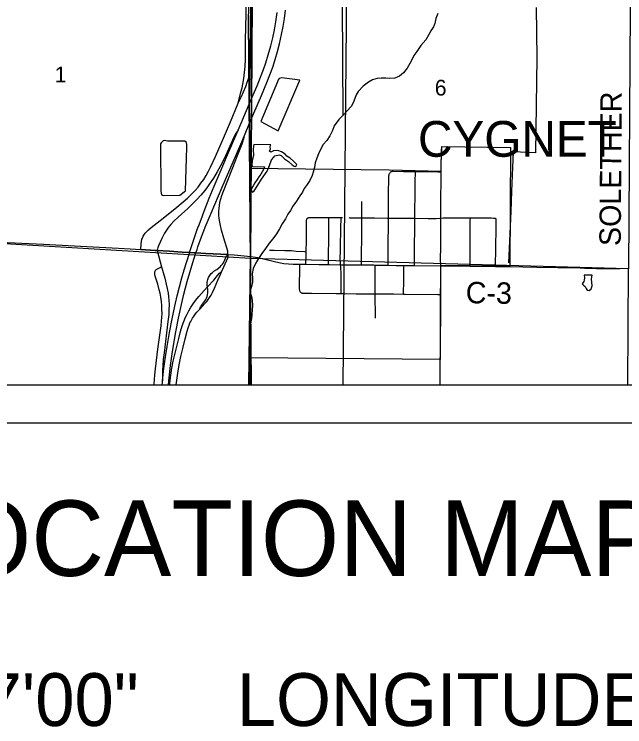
# Model space of a CAD drawing. Extents: x 0 to 39.4, y 0 to 22.
# Drawn here: x 4.739 to 6.358, y 13.194 to 15.083 of the extents above; entities that cross this region are included whole.
import ezdxf

# ---------------------------------------------------------------- set-up
doc = ezdxf.new("R2010")
doc.units = 0
for name, color, linetype in [('Default', 7, 'Continuous'), ('GM_X_City_Street', 7, 'Continuous'), ('GM_X_Corporation', 7, 'Continuous'), ('GM_X_Corporation_Text', 7, 'Continuous'), ('GM_X_County_Road', 7, 'Continuous'), ('GM_X_County_Road_Text', 7, 'Continuous'), ('GM_X_Interchange_Ramps', 7, 'Continuous'), ('GM_X_Interstate_Route', 7, 'Continuous'), ('GM_X_Minor_Lake', 7, 'Continuous'), ('GM_X_Minor_River', 7, 'Continuous'), ('GM_X_Rail_Line', 7, 'Continuous'), ('GM_X_Section', 7, 'Continuous'), ('GM_X_Section_Text', 7, 'Continuous'), ('GM_X_State_Route', 7, 'Continuous'), ('GM_X_Township_Road', 7, 'Continuous'), ('GM_X_Township_Road_Text', 7, 'Continuous'), ('SH_Data', 7, 'Continuous'), ('SH_Text', 7, 'Continuous')]:
    doc.layers.add(name, color=color, linetype=linetype)

msp = doc.modelspace()

# ---------------------------------------------------------------- linework, layer by layer
at = {"layer": 'Default'}
for points in [[(4.3575, 14.1), (5.3634, 14.1), (5.3657, 14.4352), (4.3571, 14.4954)], [(5.3634, 14.1), (6.3661, 14.1), (6.3684, 14.4076), (5.3657, 14.4352)]]:
    msp.add_lwpolyline(points, close=True, dxfattribs=at)
at = {"layer": 'GM_X_City_Street'}
for points in [[(5.7305, 14.4176), (5.7305, 14.4227), (5.7308, 14.4538), (5.7307, 14.4667), (5.731, 14.4898), (5.7313, 14.5091), (5.7313, 14.5284), (5.7313, 14.5424), (5.7313, 14.5469), (5.7315, 14.5599), (5.7316, 14.5731), (5.7318, 14.6079), (5.7319, 14.6212), (5.732, 14.6352), (5.732, 14.6481), (5.7324, 14.6544), (5.7329, 14.6574), (5.7333, 14.6589), (5.7339, 14.6603), (5.7347, 14.6617), (5.7355, 14.6629), (5.7366, 14.664), (5.7375, 14.6649), (5.7389, 14.6658), (5.7404, 14.6664)], [(5.7404, 14.6664), (5.7419, 14.6667), (5.7433, 14.6668), (5.7712, 14.666), (5.7957, 14.6657), (5.8028, 14.6658), (5.8171, 14.6658), (5.8351, 14.6659), (5.8477, 14.6656), (5.8624, 14.6654), (5.8711, 14.6652)], [(5.8003, 14.4168), (5.8003, 14.4203), (5.8003, 14.4287), (5.8002, 14.4336), (5.8002, 14.4376), (5.8004, 14.4507), (5.8004, 14.4588), (5.8005, 14.4667), (5.8006, 14.4744), (5.8009, 14.4879), (5.801, 14.4944), (5.801, 14.5018), (5.8012, 14.5109), (5.8012, 14.5162), (5.8012, 14.5217), (5.8013, 14.5316), (5.8013, 14.5419), (5.8013, 14.5434), (5.8013, 14.5531), (5.8015, 14.5623), (5.8017, 14.5686), (5.8017, 14.5772), (5.8019, 14.5881), (5.8021, 14.5959), (5.8022, 14.6022), (5.8022, 14.6051), (5.8021, 14.6092), (5.8022, 14.6256), (5.8025, 14.6473), (5.8027, 14.6566), (5.8027, 14.6597), (5.8028, 14.6658)], [(5.6598, 14.4184), (5.6598, 14.4235), (5.6598, 14.4266), (5.6601, 14.4579), (5.6603, 14.4798), (5.6604, 14.5143), (5.6605, 14.5393), (5.6605, 14.5433), (5.6607, 14.568), (5.6606, 14.5861)], [(5.5119, 14.4199), (5.5121, 14.425), (5.5127, 14.4404), (5.513, 14.4533), (5.5136, 14.4828), (5.514, 14.5289), (5.5141, 14.5345), (5.5142, 14.5366), (5.5144, 14.5384), (5.5147, 14.5401), (5.5153, 14.5416)], [(5.5153, 14.5416), (5.5162, 14.5424), (5.5174, 14.5431), (5.5188, 14.5436), (5.5204, 14.5439), (5.522, 14.5441), (5.5234, 14.5442), (5.5251, 14.5443), (5.5347, 14.5444), (5.5408, 14.5443), (5.5441, 14.5442), (5.5473, 14.5442), (5.5502, 14.5442), (5.5533, 14.5443), (5.569, 14.5442), (5.5734, 14.5441), (5.5972, 14.5438), (5.606, 14.5438), (5.6098, 14.5438)], [(5.5721, 14.4192), (5.5721, 14.4249), (5.5721, 14.4311), (5.5724, 14.4498), (5.5729, 14.4802), (5.573, 14.5019), (5.5733, 14.5358), (5.5734, 14.5441)], [(5.6045, 14.4188), (5.6041, 14.4227), (5.6037, 14.4265), (5.6036, 14.4294), (5.6041, 14.462), (5.6051, 14.518), (5.6059, 14.5407), (5.606, 14.5438)], [(5.626, 14.5437), (5.6291, 14.5436), (5.6508, 14.5434), (5.6605, 14.5433), (5.6941, 14.5428), (5.7281, 14.5424), (5.7313, 14.5424), (5.7591, 14.5423), (5.8013, 14.5419), (5.8365, 14.5416), (5.8582, 14.5418), (5.8674, 14.5423), (5.8701, 14.5427), (5.8766, 14.5436), (5.8828, 14.5436), (5.923, 14.5433), (5.9487, 14.5431), (5.9756, 14.5428), (5.9911, 14.543), (6.0035, 14.543), (6.0103, 14.5427), (6.0127, 14.5425), (6.0142, 14.5421), (6.0151, 14.5418), (6.016, 14.5412), (6.0167, 14.5404)], [(5.9476, 14.4154), (5.9478, 14.4226), (5.9481, 14.4349), (5.9481, 14.4438), (5.948, 14.4562), (5.9481, 14.4654), (5.9481, 14.4716), (5.9483, 14.4931), (5.9486, 14.5362), (5.9487, 14.5431)], [(6.0157, 14.4145), (6.0158, 14.4207), (6.0164, 14.4578), (6.0174, 14.5227), (6.0175, 14.5358), (6.0174, 14.5377), (6.0172, 14.5392), (6.0167, 14.5404)], [(5.4159, 14.4575), (5.4282, 14.4572), (5.456, 14.4569), (5.4745, 14.4563), (5.4868, 14.4552), (5.5083, 14.4537), (5.513, 14.4533)], [(5.4982, 14.3459), (5.4973, 14.3471), (5.4966, 14.3486), (5.4959, 14.3507), (5.4956, 14.3547), (5.4954, 14.3619), (5.4956, 14.3777), (5.4959, 14.393), (5.4961, 14.4061), (5.4963, 14.4163), (5.4964, 14.42)], [(5.6057, 14.3425), (5.6058, 14.3488), (5.606, 14.358), (5.6061, 14.3825), (5.6057, 14.4008), (5.6053, 14.4066), (5.6049, 14.413), (5.6045, 14.4188)], [(5.6968, 14.2771), (5.6966, 14.2838), (5.6964, 14.3351), (5.6963, 14.3417), (5.6961, 14.3605), (5.6959, 14.397), (5.6959, 14.4093), (5.6958, 14.4181)], [(5.7717, 14.3412), (5.7717, 14.3466), (5.7719, 14.3714), (5.7725, 14.4086), (5.7726, 14.4117), (5.7727, 14.417)], [(5.4982, 14.3459), (5.4991, 14.3451), (5.5, 14.3446), (5.5012, 14.3442), (5.5025, 14.3438), (5.5057, 14.3434), (5.5086, 14.3432), (5.5272, 14.343), (5.5926, 14.3425), (5.6057, 14.3425), (5.6143, 14.3425), (5.6453, 14.3421), (5.6763, 14.3419), (5.6963, 14.3417), (5.7447, 14.3413), (5.7717, 14.3412), (5.7758, 14.3411), (5.8628, 14.3403), (5.8698, 14.3402)]]:
    msp.add_lwpolyline(points, dxfattribs=at)
at = {"layer": 'GM_X_Corporation'}
msp.add_lwpolyline([(5.8709, 14.6669), (5.8713, 14.6907), (5.8717, 14.7058), (5.8721, 14.7144), (5.8725, 14.7232), (5.8729, 14.7292), (5.873, 14.732), (6.0549, 14.7298), (6.0538, 14.4143), (6.0145, 14.4148), (5.9473, 14.4156), (5.8696, 14.4166), (5.8696, 14.3408), (5.8686, 14.1677), (5.3636, 14.1716), (5.3666, 14.4404), (5.3638, 14.6746), (5.7333, 14.6707)], close=True, dxfattribs=at)
at = {"layer": 'GM_X_County_Road'}
for p, q in [((5.6958, 14.4181), (5.7305, 14.4176)), ((5.8003, 14.4168), (5.8699, 14.4163)), ((6.0157, 14.4145), (6.0522, 14.4139))]:
    msp.add_line(p, q, dxfattribs=at)
for points in [[(4.3528, 14.4954), (4.354, 14.4954), (4.3695, 14.495), (4.4129, 14.4928), (4.4533, 14.4912), (4.4998, 14.4886), (4.624, 14.4826), (4.8165, 14.4733), (4.9314, 14.4674), (5.0151, 14.4626), (5.0462, 14.4607), (5.0742, 14.4592)], [(5.0742, 14.4592), (5.1128, 14.4566), (5.1178, 14.4564)], [(5.1178, 14.4564), (5.1501, 14.4546), (5.1844, 14.4525), (5.2037, 14.4514), (5.2155, 14.4507), (5.2206, 14.4504), (5.2467, 14.449), (5.3056, 14.4457)], [(5.2311, 14.3014), (5.2321, 14.3043), (5.2334, 14.307), (5.2346, 14.3091), (5.2366, 14.3118), (5.2381, 14.3141), (5.2404, 14.3176), (5.244, 14.3225), (5.2465, 14.3265), (5.2486, 14.3306), (5.2502, 14.3349), (5.2514, 14.3394), (5.2521, 14.344), (5.2523, 14.3487), (5.252, 14.3533), (5.2511, 14.3598), (5.2507, 14.3625), (5.2505, 14.3672), (5.2507, 14.3718), (5.2513, 14.3764), (5.252, 14.3794), (5.2529, 14.3824), (5.2541, 14.3852), (5.2555, 14.388), (5.2572, 14.3906), (5.259, 14.3931), (5.2611, 14.3954), (5.2645, 14.3986), (5.2682, 14.4014), (5.2759, 14.4066), (5.2809, 14.4102), (5.2845, 14.4132), (5.2878, 14.4165), (5.2908, 14.42), (5.2934, 14.4238), (5.2957, 14.4279), (5.2976, 14.4321), (5.2999, 14.439), (5.3007, 14.4407), (5.3018, 14.442), (5.3025, 14.4429), (5.3056, 14.4457)], [(5.3056, 14.4457), (5.3217, 14.4448), (5.3488, 14.4428), (5.3658, 14.4409)], [(5.3658, 14.4409), (5.3845, 14.4376), (5.3996, 14.4343), (5.4328, 14.4262), (5.4449, 14.4235), (5.4541, 14.422), (5.4665, 14.4208), (5.4789, 14.4202), (5.4964, 14.42)], [(5.1093, 14.1), (5.1094, 14.1022), (5.1115, 14.1269), (5.1131, 14.1424), (5.1199, 14.1948), (5.1258, 14.2379), (5.1283, 14.2564), (5.1296, 14.2688), (5.1304, 14.2797), (5.1306, 14.289), (5.1304, 14.3), (5.1298, 14.3108), (5.1288, 14.3217), (5.1273, 14.3325), (5.1253, 14.3433), (5.1232, 14.3524), (5.1191, 14.3674), (5.1127, 14.3882), (5.1117, 14.3927), (5.1113, 14.3957), (5.1114, 14.3971), (5.1115, 14.3986), (5.1118, 14.4), (5.1122, 14.4014), (5.1128, 14.4027), (5.1135, 14.4039), (5.1144, 14.4051), (5.1154, 14.4062), (5.1167, 14.4072), (5.1186, 14.4083), (5.1293, 14.4135)], [(5.4964, 14.42), (5.5069, 14.4199), (5.5119, 14.4199)], [(5.5119, 14.4199), (5.5471, 14.4194), (5.5721, 14.4192)], [(5.5721, 14.4192), (5.575, 14.4192), (5.6045, 14.4188)], [(5.6045, 14.4188), (5.6122, 14.4188), (5.6307, 14.4187), (5.6598, 14.4184)], [(5.6598, 14.4184), (5.6926, 14.4182), (5.6958, 14.4181)], [(5.7305, 14.4176), (5.7514, 14.4172), (5.7727, 14.417)], [(5.7727, 14.417), (5.7875, 14.4169), (5.8003, 14.4168)], [(5.8699, 14.4163), (5.8891, 14.416), (5.9476, 14.4154)], [(5.9476, 14.4154), (5.9946, 14.4149), (6.0157, 14.4145)], [(6.0522, 14.4139), (6.0876, 14.4134), (6.1249, 14.4126), (6.1808, 14.4118), (6.2398, 14.4103), (6.2522, 14.4099), (6.2833, 14.4086), (6.3082, 14.4085), (6.3455, 14.4089), (6.3686, 14.4093)], [(5.2311, 14.3014), (5.2445, 14.3157), (5.2495, 14.3217), (5.2532, 14.3267), (5.2568, 14.3318), (5.2608, 14.3385), (5.2644, 14.3454), (5.2697, 14.3568), (5.2791, 14.3783), (5.285, 14.3915), (5.2896, 14.4021)], [(5.1679, 14.1), (5.1705, 14.1192), (5.1735, 14.1376), (5.1771, 14.1575), (5.1809, 14.1758), (5.1858, 14.197), (5.1922, 14.2227), (5.1971, 14.2423), (5.1997, 14.2513), (5.2024, 14.2586), (5.2048, 14.2644), (5.2069, 14.2686), (5.2115, 14.2768), (5.2157, 14.2834), (5.2194, 14.2885), (5.2234, 14.2933), (5.2311, 14.3014)]]:
    msp.add_lwpolyline(points, dxfattribs=at)
at = {"layer": 'GM_X_Interchange_Ramps'}
msp.add_line((5.1178, 14.4564), (5.1293, 14.4135), dxfattribs=at)
for points in [[(5.3324, 14.7755), (5.3281, 14.7691), (5.3249, 14.7639), (5.3219, 14.7585), (5.3175, 14.7488), (5.3036, 14.7174), (5.2943, 14.6977), (5.2858, 14.6811), (5.2767, 14.6647), (5.2671, 14.6487), (5.2586, 14.6356), (5.2514, 14.6254), (5.2438, 14.6155), (5.2338, 14.6036), (5.2232, 14.5921), (5.2123, 14.581), (5.1987, 14.5682), (5.1733, 14.5451), (5.1621, 14.5342), (5.1536, 14.5251), (5.1476, 14.518), (5.1421, 14.5104), (5.1371, 14.5025), (5.1341, 14.4971), (5.13, 14.4887), (5.1212, 14.4688), (5.1198, 14.4649), (5.1187, 14.461), (5.1178, 14.4564)], [(5.3056, 14.4457), (5.3056, 14.4523), (5.3054, 14.4538), (5.3051, 14.4552), (5.2945, 14.4895), (5.2885, 14.5105), (5.2855, 14.5226), (5.2836, 14.5318), (5.2823, 14.5411), (5.2816, 14.5504), (5.2815, 14.5598), (5.282, 14.5691), (5.2827, 14.5753), (5.2843, 14.5845), (5.2866, 14.5936), (5.2893, 14.6026), (5.2934, 14.6143), (5.3169, 14.6722), (5.333, 14.7126), (5.3348, 14.7171), (5.3412, 14.7345), (5.3429, 14.7391), (5.3457, 14.7472), (5.3469, 14.7506), (5.3477, 14.7532), (5.3482, 14.7558), (5.349, 14.7613)], [(5.1293, 14.4135), (5.1381, 14.3828), (5.142, 14.3677), (5.1446, 14.3555), (5.1468, 14.3432), (5.148, 14.3339), (5.1488, 14.3246), (5.1493, 14.3121), (5.1491, 14.2996), (5.1483, 14.2872), (5.1464, 14.2686), (5.1359, 14.185), (5.1339, 14.1679), (5.1325, 14.1509), (5.1319, 14.1397), (5.1316, 14.126), (5.132, 14.1113)]]:
    msp.add_lwpolyline(points, dxfattribs=at)
at = {"layer": 'GM_X_Interstate_Route'}
msp.add_line((5.2271, 14.5201), (5.2342, 14.5391), dxfattribs=at)
for points in [[(2.1, 15.507), (2.1, 14.1), (5.3613, 14.1), (5.3656, 14.4414), (5.3638, 14.6746), (5.3629, 14.7948), (5.3615, 14.845), (5.3635, 14.9304), (5.3699, 15.3511)], [(5.3699, 15.3511), (5.3635, 14.9304), (5.3615, 14.845), (5.3629, 14.7948), (5.3638, 14.6746), (5.3656, 14.4414), (5.3613, 14.1), (8.9, 14.1), (8.9, 15.3132)], [(5.349, 14.7613), (5.3631, 14.7943), (5.3944, 14.8673), (5.4089, 14.9017), (5.4168, 14.9219), (5.4242, 14.9423), (5.4309, 14.963), (5.4369, 14.9839), (5.4423, 15.0049), (5.4478, 15.0291), (5.4521, 15.0505), (5.4557, 15.0719), (5.4586, 15.0934)], [(5.3324, 14.7755), (5.3403, 14.7941), (5.3617, 14.8445), (5.363, 14.8474), (5.3826, 14.8931), (5.3922, 14.9161), (5.3999, 14.9364), (5.406, 14.9541), (5.4125, 14.9749), (5.4191, 14.9989), (5.4244, 15.02), (5.429, 15.0413), (5.4328, 15.0628), (5.4365, 15.0874)], [(5.2342, 14.5391), (5.2423, 14.561), (5.2558, 14.5957), (5.2688, 14.6273), (5.2848, 14.6644), (5.3043, 14.7102), (5.3324, 14.7755)], [(5.2455, 14.5184), (5.2611, 14.5558), (5.2903, 14.6245), (5.3393, 14.7387), (5.349, 14.7613)], [(5.1309, 14.1), (5.1315, 14.1066), (5.132, 14.1113), (5.1356, 14.1437), (5.1396, 14.1745), (5.1439, 14.2021), (5.1503, 14.2388), (5.1575, 14.2754), (5.1645, 14.3088), (5.1709, 14.3361), (5.1833, 14.3842), (5.1893, 14.4051), (5.2031, 14.4496), (5.2037, 14.4514), (5.2158, 14.488), (5.226, 14.5173), (5.2271, 14.5201)], [(5.2235, 14.4592), (5.2258, 14.4661), (5.2353, 14.4924), (5.2443, 14.5156), (5.2455, 14.5184)], [(5.1477, 14.1), (5.1487, 14.1113), (5.1533, 14.1514), (5.1574, 14.1823), (5.1617, 14.2099), (5.1671, 14.2406), (5.1744, 14.2772), (5.1823, 14.3136), (5.1889, 14.3409), (5.1975, 14.374), (5.2068, 14.4069), (5.216, 14.4366), (5.2206, 14.4504), (5.2235, 14.4592)]]:
    msp.add_lwpolyline(points, dxfattribs=at)
at = {"layer": 'GM_X_Minor_Lake'}
for p, q in [((5.4371, 14.9037), (5.3926, 14.7987)), ((5.4194, 14.7364), (5.3739, 14.7374)), ((5.1781, 14.6035), (5.1931, 14.6146)), ((6.2721, 14.3911), (6.2505, 14.3914))]:
    msp.add_line(p, q, dxfattribs=at)
for points in [[(5.3926, 14.7987), (5.4385, 14.7734), (5.4959, 14.9082), (5.4486, 14.9142), (5.4414, 14.9127), (5.4386, 14.9091), (5.4371, 14.9037)], [(5.1931, 14.6146), (5.1967, 14.7305), (5.1968, 14.7369), (5.1957, 14.7426), (5.1912, 14.7465), (5.1859, 14.7466), (5.145, 14.7468), (5.1374, 14.7484), (5.1332, 14.7473), (5.1286, 14.7424), (5.127, 14.7394), (5.1262, 14.7364), (5.1271, 14.6144), (5.1281, 14.6083), (5.1296, 14.6045), (5.1315, 14.6037), (5.1356, 14.6022), (5.1781, 14.6035)], [(5.3739, 14.7374), (5.3735, 14.7336), (5.3726, 14.7245), (5.3731, 14.7082), (5.3699, 14.6953), (5.3685, 14.6832), (5.3708, 14.679), (5.4026, 14.6785), (5.3995, 14.6713), (5.3925, 14.6593), (5.3874, 14.6521), (5.3828, 14.6446), (5.3769, 14.636), (5.3726, 14.6277), (5.368, 14.6213), (5.3675, 14.6156), (5.3709, 14.6113), (5.3751, 14.6147), (5.3848, 14.6298), (5.3949, 14.646), (5.4093, 14.667), (5.4155, 14.6817), (5.4215, 14.6969), (5.4273, 14.7044), (5.4303, 14.7074), (5.441, 14.7099), (5.4467, 14.7083), (5.4553, 14.6994), (5.4658, 14.6928), (5.4755, 14.6836), (5.4815, 14.6804), (5.4857, 14.6789), (5.488, 14.6849), (5.4798, 14.693), (5.4708, 14.7011), (5.4614, 14.7065), (5.457, 14.7119), (5.4472, 14.7178), (5.4381, 14.7217), (5.426, 14.7207), (5.4191, 14.7174), (5.4161, 14.7197), (5.4185, 14.7258), (5.4178, 14.7315), (5.4178, 14.7334), (5.4194, 14.7364)], [(6.2505, 14.3914), (6.2515, 14.3838), (6.251, 14.3777), (6.2495, 14.3743), (6.2456, 14.3683), (6.249, 14.3648), (6.2531, 14.3613), (6.256, 14.3556), (6.2586, 14.3518), (6.2635, 14.3509), (6.2693, 14.355), (6.2717, 14.3626), (6.2711, 14.3729), (6.2704, 14.3809), (6.2713, 14.3865), (6.2721, 14.3911)]]:
    msp.add_lwpolyline(points, dxfattribs=at)
at = {"layer": 'GM_X_Minor_River'}
msp.add_line((5.3633, 14.1), (5.3642, 14.2325), dxfattribs=at)
for points in [[(5.6112, 14.8154), (5.6092, 15.1099)], [(6.1236, 15.1012), (6.1254, 14.967), (6.1212, 14.7151), (6.062, 14.7185), (6.0582, 14.6143), (6.0559, 14.5604), (6.0498, 14.4243)], [(5.862, 15.0845), (5.8571, 15.072), (5.8541, 15.0587), (5.8506, 15.0492), (5.8442, 15.0389), (5.8389, 15.0294), (5.8309, 15.0153), (5.8176, 14.9998), (5.8063, 14.9842), (5.799, 14.9739), (5.793, 14.9625), (5.788, 14.9523), (5.7812, 14.9397), (5.771, 14.9279), (5.7611, 14.9184), (5.7482, 14.9131), (5.7342, 14.9124), (5.7247, 14.9131), (5.7118, 14.9139), (5.7011, 14.9127), (5.6886, 14.9089), (5.6784, 14.9029), (5.6647, 14.8926), (5.6514, 14.8785), (5.6454, 14.869), (5.642, 14.8595), (5.6374, 14.8478), (5.6325, 14.8379), (5.6222, 14.8265), (5.6112, 14.8154), (5.5998, 14.8037), (5.5877, 14.7869), (5.5831, 14.7744), (5.5756, 14.7603), (5.5683, 14.7486), (5.5585, 14.7379), (5.5513, 14.7239), (5.546, 14.7128), (5.5414, 14.7014), (5.5372, 14.6889), (5.535, 14.6764), (5.5315, 14.6646), (5.5289, 14.6551), (5.5224, 14.6422), (5.5156, 14.6319), (5.508, 14.6212), (5.5031, 14.6114), (5.4962, 14.6011), (5.4871, 14.587), (5.478, 14.5737), (5.4716, 14.5627), (5.4648, 14.5532), (5.4579, 14.5407), (5.4496, 14.527), (5.442, 14.5141), (5.434, 14.5008), (5.4245, 14.4875), (5.4147, 14.4757), (5.4048, 14.4616), (5.3953, 14.4483), (5.3862, 14.435), (5.3786, 14.4221), (5.3725, 14.4084), (5.3699, 14.3944), (5.3703, 14.3841), (5.3707, 14.3716), (5.368, 14.3613), (5.3634, 14.348), (5.368, 14.3347), (5.3699, 14.3248), (5.371, 14.3107), (5.3699, 14.2993), (5.3691, 14.2872), (5.368, 14.2754), (5.3662, 14.2691), (5.3655, 14.2596), (5.3642, 14.2325)]]:
    msp.add_lwpolyline(points, dxfattribs=at)
at = {"layer": 'GM_X_Rail_Line'}
for points in [[(5.6115, 14.1), (5.6226, 15.3413), (5.6228, 15.3801), (5.635, 16.7601), (5.6441, 17.4388), (5.6457, 18.044), (5.6539, 18.4301), (5.6611, 19.3588), (5.6728, 20.3992), (5.6755, 20.8483), (5.6758, 20.9)], [(5.368, 14.1), (5.3598, 15.0692), (5.3695, 15.387)]]:
    msp.add_lwpolyline(points, dxfattribs=at)
at = {"layer": 'GM_X_Section'}
for points in [[(4.3536, 15.4159), (4.3695, 15.415), (5.3717, 15.3889), (5.3657, 14.4352), (4.3571, 14.4954)], [(5.3717, 15.3889), (6.3442, 15.3693), (6.3741, 15.3693), (6.3684, 14.4076), (5.3657, 14.4352)]]:
    msp.add_lwpolyline(points, close=True, dxfattribs=at)
at = {"layer": 'GM_X_State_Route'}
for points in [[(5.3324, 14.8471), (5.3396, 14.876), (5.3428, 14.8881), (5.3448, 14.8973), (5.3474, 14.9129), (5.3494, 14.9284), (5.3509, 14.9441), (5.3518, 14.9629), (5.3522, 14.9881), (5.3523, 15.013), (5.3547, 15.1199), (5.3563, 15.1636), (5.3611, 15.2446), (5.3635, 15.2852), (5.3654, 15.332), (5.366, 15.3846)], [(5.3638, 14.9299), (5.3648, 14.9356), (5.3666, 14.9479), (5.3676, 14.9602), (5.3683, 14.9788), (5.3691, 15.0348), (5.3719, 15.1779), (5.3733, 15.2619), (5.3756, 15.3667)], [(5.3324, 14.8471), (5.3406, 14.863), (5.3528, 14.891), (5.3569, 14.9025), (5.3596, 14.9114), (5.3625, 14.9234), (5.3638, 14.9299)], [(5.0742, 14.4592), (5.0754, 14.4745), (5.0761, 14.4806), (5.0774, 14.4865), (5.0784, 14.4894), (5.0795, 14.4923), (5.0808, 14.495), (5.084, 14.5002), (5.0859, 14.5026), (5.09, 14.5071), (5.0945, 14.5114), (5.1016, 14.5173), (5.1335, 14.5422), (5.1699, 14.5715), (5.1868, 14.5853), (5.1984, 14.5956), (5.2097, 14.6064), (5.2183, 14.6155), (5.2265, 14.6249), (5.234, 14.6349), (5.2411, 14.6452), (5.2478, 14.6557), (5.254, 14.6666), (5.2595, 14.6778), (5.2723, 14.7062), (5.2933, 14.7548), (5.3119, 14.7976), (5.3324, 14.8471)], [(5.1178, 14.4564), (5.1128, 14.4566), (5.0742, 14.4592)], [(5.3056, 14.4457), (5.2467, 14.449), (5.2206, 14.4504), (5.2155, 14.4507), (5.2037, 14.4514), (5.1844, 14.4525), (5.1501, 14.4546), (5.1178, 14.4564)], [(5.1509, 14.1), (5.1513, 14.1047), (5.1539, 14.1263), (5.1568, 14.1448), (5.1604, 14.1631), (5.1646, 14.1812), (5.175, 14.2235), (5.1799, 14.2415), (5.1843, 14.2564), (5.1884, 14.2682), (5.1931, 14.2797), (5.197, 14.2882), (5.2014, 14.2964), (5.2061, 14.3045), (5.2129, 14.3148), (5.2204, 14.3248), (5.2283, 14.3344), (5.2428, 14.3507), (5.2511, 14.3598), (5.268, 14.3782), (5.2781, 14.39), (5.2832, 14.3961), (5.2862, 14.3995), (5.2896, 14.4021), (5.2946, 14.4134), (5.3014, 14.429), (5.305, 14.4372), (5.3055, 14.4387), (5.3058, 14.4399), (5.3059, 14.4414), (5.3056, 14.4457)]]:
    msp.add_lwpolyline(points, dxfattribs=at)
at = {"layer": 'GM_X_Township_Road'}
msp.add_line((5.8686, 14.1), (5.869, 14.1673), dxfattribs=at)
for points in [[(5.8711, 14.6652), (5.8712, 14.6664), (5.8715, 14.6901), (5.8719, 14.7052), (5.8723, 14.7138), (5.8727, 14.7226), (5.8731, 14.7286)], [(5.8701, 14.5427), (5.8702, 14.5981), (5.8708, 14.6384), (5.8711, 14.6652)], [(5.8699, 14.4163), (5.8698, 14.4341), (5.8699, 14.4651), (5.87, 14.5086), (5.8701, 14.5333), (5.8701, 14.5427)], [(5.8698, 14.3402), (5.8701, 14.3731), (5.8699, 14.4163)], [(5.869, 14.1673), (5.8691, 14.1787), (5.8694, 14.2776), (5.8698, 14.3329), (5.8698, 14.3402)]]:
    msp.add_lwpolyline(points, dxfattribs=at)
at = {"layer": 'SH_Data'}
for p, q in [((2.1, 14.1), (8.9, 14.1)), ((2, 14), (9, 14))]:
    msp.add_line(p, q, dxfattribs=at)

# ---------------------------------------------------------------- texts
at = {"layer": 'GM_X_Corporation_Text'}
msp.add_text('CYGNET', height=0.0947, rotation=0, dxfattribs=at).set_placement((5.8097, 14.7051))
at = {"layer": 'GM_X_County_Road_Text'}
msp.add_text('C-3', height=0.05682, rotation=359.0818, dxfattribs=at).set_placement((5.9361, 14.3169))
at = {"layer": 'GM_X_Section_Text'}
for s, p in [('1', (4.8459, 14.9023)), ('6', (5.8543, 14.8673))]:
    msp.add_text(s, height=0.0419, rotation=0, dxfattribs=at).set_placement(p)
at = {"layer": 'GM_X_Township_Road_Text'}
msp.add_text('SOLETHER', height=0.05682, rotation=89.5986, dxfattribs=at).set_placement((6.3477, 14.4682))
at = {"layer": 'SH_Text'}
for s, height, p in [('LOCATION MAP', 0.2, (4.4269, 13.5938)), ('LATITUDE:  N41°17\'00"     LONGITUDE:  W83°39\'10"', 0.14, (3.071, 13.1959))]:
    msp.add_text(s, height=height, dxfattribs=at).set_placement(p)

doc.saveas('drawing.dxf')
